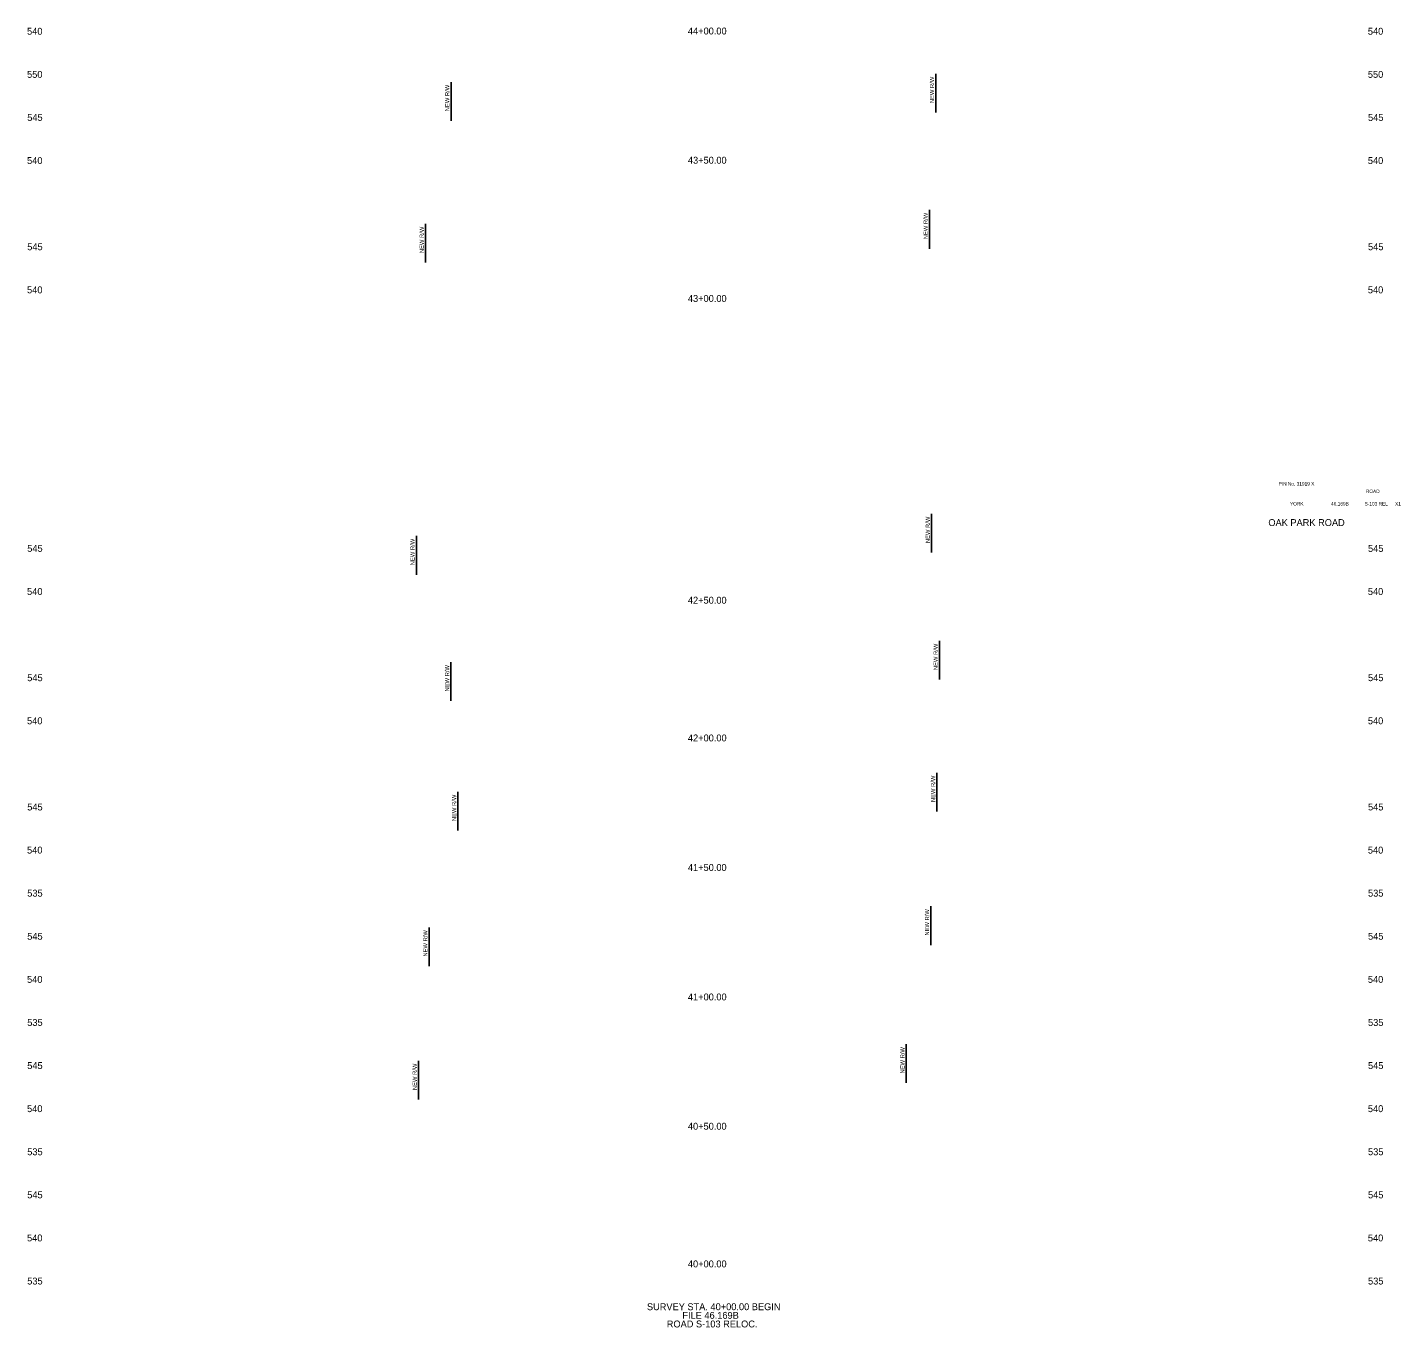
# Model space of a CAD drawing. Extents: x 1001 to 1161, y 1005 to 3518.
# Drawn here: x 1001.2 to 1160.4, y 1005.1 to 1155.9 of the extents above; entities that cross this region are included whole.
import ezdxf

# ---------------------------------------------------------------- set-up
doc = ezdxf.new("R2010")
doc.units = 0
for name, color, linetype in [('RD_SHT_TX', 7, 'Continuous'), ('RD_XS_NewRW', 7, 'Continuous'), ('RD_XS_TX_Elev_EX', 7, 'Continuous'), ('RD_XS_TX_Notes', 7, 'Continuous'), ('RD_XS_TX_Station', 7, 'Continuous')]:
    doc.layers.add(name, color=color, linetype=linetype)

msp = doc.modelspace()

# ---------------------------------------------------------------- linework, layer by layer
at = {"layer": 'RD_XS_NewRW'}
for p, q in [((1106.53, 1150.56), (1106.53, 1146.06)), ((1050.31, 1149.61), (1050.31, 1145.11)), ((1105.8, 1134.77), (1105.8, 1130.27)), ((1047.36, 1133.16), (1047.36, 1128.66)), ((1106.05, 1099.52), (1106.05, 1095.02)), ((1046.29, 1096.95), (1046.29, 1092.45)), ((1106.96, 1084.78), (1106.96, 1080.28)), ((1050.3, 1082.3), (1050.3, 1077.8)), ((1106.66, 1069.47), (1106.66, 1064.97)), ((1051.11, 1067.26), (1051.11, 1062.76)), ((1105.97, 1053.98), (1105.97, 1049.48)), ((1047.78, 1051.53), (1047.78, 1047.03)), ((1103.11, 1037.98), (1103.11, 1033.48)), ((1046.55, 1036.06), (1046.55, 1031.56))]:
    msp.add_line(p, q, dxfattribs=at)

# ---------------------------------------------------------------- texts
at = {"layer": 'RD_SHT_TX'}
for s, height, p in [('PIN No. 31919 X', 0.4, (1146.29, 1102.8)), ('ROAD', 0.4, (1156.41, 1101.93)), ('YORK', 0.4, (1147.61, 1100.48)), ('46.169B', 0.4, (1152.37, 1100.48)), ('S-103 REL', 0.4, (1156.26, 1100.48)), ('X1', 0.4, (1159.8, 1100.48)), ('OAK PARK ROAD', 0.8, (1145.1, 1098.1))]:
    msp.add_text(s, height=height, dxfattribs=at).set_placement(p)
at = {"layer": 'RD_XS_NewRW'}
for p in [(1106.33, 1147.16), (1050.11, 1146.22), (1105.6, 1131.37), (1047.16, 1129.76), (1105.85, 1096.12), (1046.08, 1093.55), (1106.76, 1081.38), (1050.1, 1078.9), (1106.46, 1066.07), (1050.91, 1063.86), (1105.76, 1050.58), (1047.58, 1048.14), (1102.91, 1034.58), (1046.35, 1032.66)]:
    msp.add_text('NEW R/W ', height=0.488, rotation=90, dxfattribs=at).set_placement(p)
at = {"layer": 'RD_XS_TX_Elev_EX'}
for s, p in [('540', (1001.14, 1155.1)), ('540', (1156.64, 1155.1)), ('550', (1001.14, 1150.1)), ('550', (1156.64, 1150.1)), ('545', (1001.16, 1145.1)), ('545', (1156.66, 1145.1)), ('540', (1001.14, 1140.1)), ('540', (1156.64, 1140.1)), ('545', (1001.16, 1130.1)), ('545', (1156.66, 1130.1)), ('540', (1001.14, 1125.1)), ('540', (1156.64, 1125.1)), ('545', (1001.16, 1095.1)), ('545', (1156.66, 1095.1)), ('540', (1001.14, 1090.1)), ('540', (1156.64, 1090.1)), ('545', (1001.16, 1080.1)), ('545', (1156.66, 1080.1)), ('540', (1001.14, 1075.1)), ('540', (1156.64, 1075.1)), ('545', (1001.16, 1065.1)), ('545', (1156.66, 1065.1)), ('540', (1001.14, 1060.1)), ('540', (1156.64, 1060.1)), ('535', (1001.16, 1055.1)), ('535', (1156.66, 1055.1)), ('545', (1001.16, 1050.1)), ('545', (1156.66, 1050.1)), ('540', (1001.14, 1045.1)), ('540', (1156.64, 1045.1)), ('535', (1001.16, 1040.1)), ('535', (1156.66, 1040.1)), ('545', (1001.16, 1035.1)), ('545', (1156.66, 1035.1)), ('540', (1001.14, 1030.1)), ('540', (1156.64, 1030.1)), ('535', (1001.16, 1025.1)), ('535', (1156.66, 1025.1)), ('545', (1001.16, 1020.1)), ('545', (1156.66, 1020.1)), ('540', (1001.14, 1015.1)), ('540', (1156.64, 1015.1)), ('535', (1001.16, 1010.1)), ('535', (1156.66, 1010.1))]:
    msp.add_text(s, height=0.8, dxfattribs=at).set_placement(p)
at = {"layer": 'RD_XS_TX_Notes'}
for s, p in [('SURVEY STA. 40+00.00 BEGIN', (1073.03, 1007.12)), ('FILE 46.169B', (1077.14, 1006.12)), ('ROAD S-103 RELOC.', (1075.33, 1005.12))]:
    msp.add_text(s, height=0.8, dxfattribs=at).set_placement(p)
at = {"layer": 'RD_XS_TX_Station'}
for s, p in [('44+00.00', (1077.78, 1155.13)), ('43+50.00', (1077.78, 1140.14)), ('43+00.00', (1077.78, 1124.1)), ('42+50.00', (1077.78, 1089.09)), ('42+00.00', (1077.78, 1073.11)), ('41+50.00', (1077.78, 1058.08)), ('41+00.00', (1077.78, 1043.06)), ('40+50.00', (1077.78, 1028.06)), ('40+00.00', (1077.78, 1012.09))]:
    msp.add_text(s, height=0.8, dxfattribs=at).set_placement(p)

doc.saveas('drawing.dxf')
